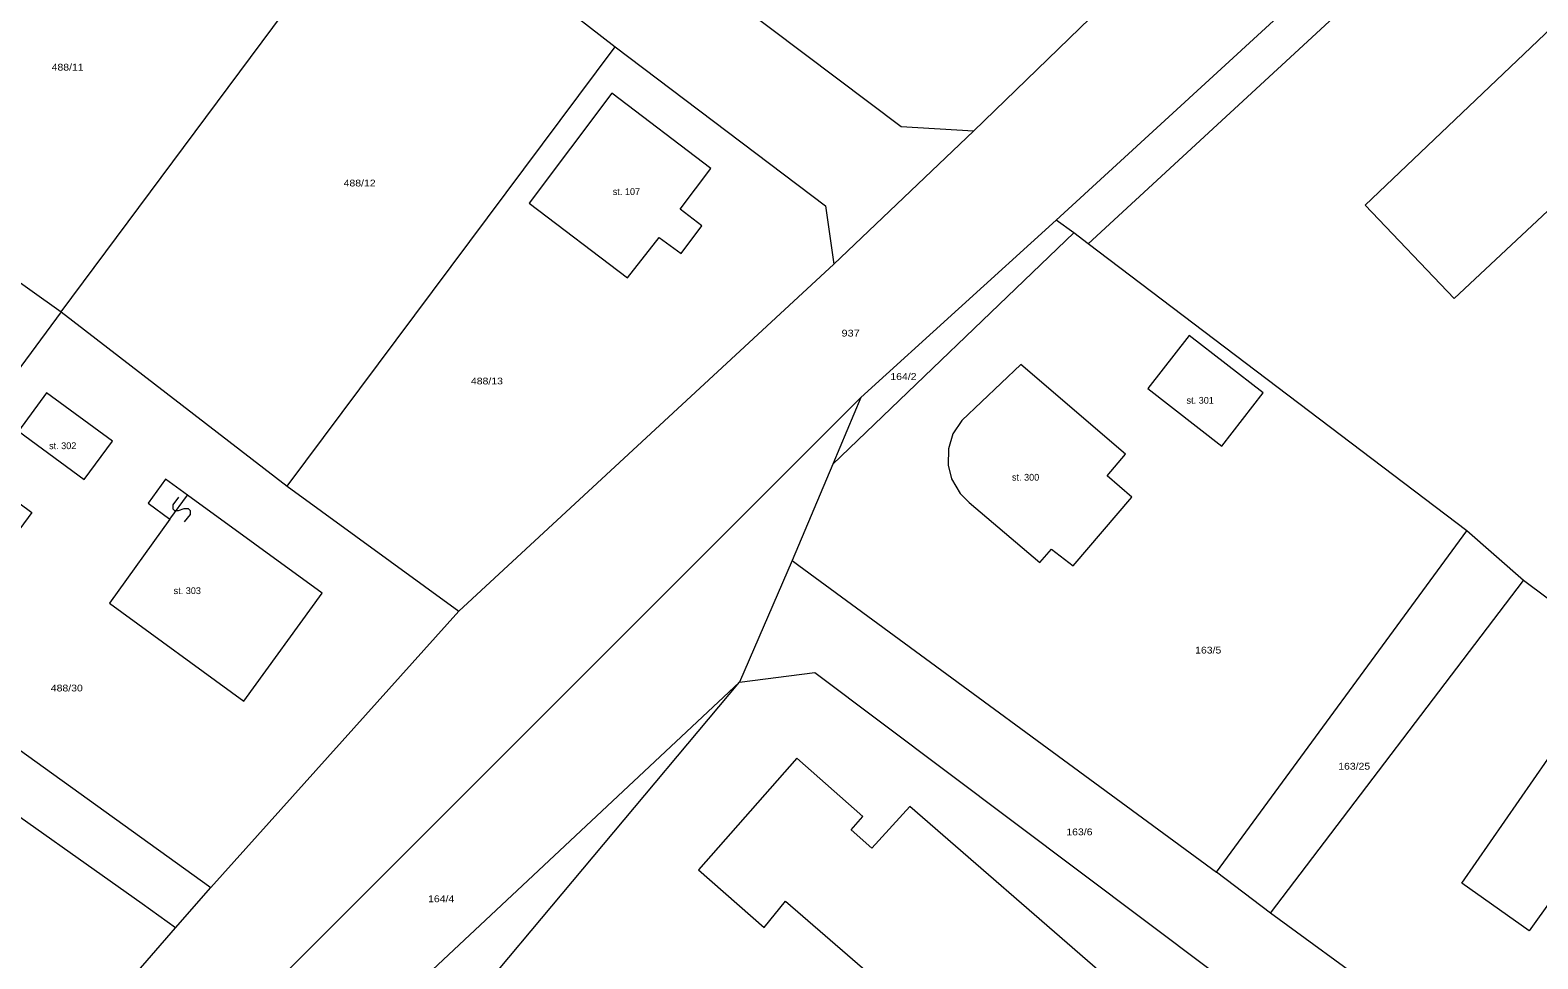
# Model space of a CAD drawing. Extents: x -694702 to -694000, y -1089746 to -1089192.
# Drawn here: x -694548.9 to -694438, y -1089557.5 to -1089489.2 of the extents above; entities that cross this region are included whole.
import ezdxf

# ---------------------------------------------------------------- set-up
doc = ezdxf.new("R2010")
doc.units = 0
doc.header["$LTSCALE"] = 0.2
doc.layers.add('50', color=7, linetype='Continuous', lineweight=13)
doc.layers.add('52', color=7, linetype='Continuous', lineweight=13)

msp = doc.modelspace()

# ---------------------------------------------------------------- linework, layer by layer
at = {"layer": '50'}
for p, q in [((-694479.49, -1089496.59), (-694449.48, -1089467.5)), ((-694546.56, -1089509.88), (-694522.45, -1089477.46)), ((-694522.45, -1089477.46), (-694505.84, -1089490.39)), ((-694529.94, -1089522.69), (-694505.84, -1089490.39)), ((-694489.75, -1089506.36), (-694479.49, -1089496.59)), ((-694473.4, -1089503.12), (-694487.76, -1089516.16)), ((-694472.12, -1089504.07), (-694473.4, -1089503.12)), ((-694472.12, -1089504.07), (-694489.83, -1089521.07)), ((-694471.06, -1089504.87), (-694472.12, -1089504.07)), ((-694443.2, -1089525.98), (-694471.06, -1089504.87)), ((-694517.33, -1089531.88), (-694489.75, -1089506.36)), ((-694546.56, -1089509.88), (-694529.94, -1089522.69)), ((-694487.76, -1089516.16), (-694545.41, -1089573.81)), ((-694487.76, -1089516.16), (-694489.83, -1089521.07)), ((-694489.83, -1089521.07), (-694492.82, -1089528.17)), ((-694529.94, -1089522.69), (-694517.33, -1089531.88)), ((-694538.57, -1089525.13), (-694537.27, -1089523.35)), ((-694461.62, -1089551.07), (-694443.2, -1089525.98)), ((-694439.04, -1089529.64), (-694443.2, -1089525.98)), ((-694492.82, -1089528.17), (-694496.69, -1089537.12)), ((-694457.65, -1089554.09), (-694439.04, -1089529.64)), ((-694435.48, -1089532.3), (-694439.04, -1089529.64)), ((-694535.56, -1089552.2), (-694517.33, -1089531.88)), ((-694457.65, -1089554.09), (-694461.62, -1089551.07)), ((-694538.16, -1089555.18), (-694535.56, -1089552.2)), ((-694430.38, -1089574.01), (-694457.65, -1089554.09))]:
    msp.add_line(p, q, dxfattribs=at)
for points in [[(-694473.4, -1089503.12), (-694446.18, -1089478.12), (-694429.84, -1089464.32)], [(-694471.06, -1089504.87), (-694439.41, -1089475.66), (-694429.16, -1089466.35)], [(-694479.49, -1089496.59), (-694484.8, -1089496.27), (-694499.16, -1089485.42)], [(-694505.84, -1089490.39), (-694490.36, -1089502.08), (-694489.75, -1089506.36)], [(-694558.62, -1089501.3), (-694546.56, -1089509.88), (-694554.38, -1089520.43)], [(-694554.38, -1089520.43), (-694548.72, -1089524.63), (-694557.45, -1089536.48), (-694535.56, -1089552.2)], [(-694492.82, -1089528.17), (-694492.32, -1089528.53), (-694461.62, -1089551.07)], [(-694538.16, -1089555.18), (-694540.61, -1089553.41), (-694565.68, -1089535.66)], [(-694496.69, -1089537.12), (-694521.2, -1089560.09), (-694538.73, -1089578.73)], [(-694450.7, -1089583.15), (-694478.25, -1089618.12), (-694527.15, -1089581.87), (-694528.98, -1089575.65), (-694496.69, -1089537.12)], [(-694496.69, -1089537.12), (-694491.16, -1089536.39), (-694442.58, -1089572.9), (-694443.91, -1089574.53)], [(-694563.76, -1089588.86), (-694559.06, -1089579.24), (-694538.16, -1089555.18)]]:
    msp.add_lwpolyline(points, dxfattribs=at)
for points in [[(-694422.23, -1089474.92), (-694450.69, -1089502.02), (-694444.14, -1089508.9), (-694415.52, -1089482.07), (-694417.72, -1089479.71)], [(-694498.81, -1089499.33), (-694506.09, -1089493.79), (-694512.16, -1089501.89), (-694504.92, -1089507.38), (-694502.59, -1089504.4), (-694500.98, -1089505.59), (-694499.47, -1089503.54), (-694501.06, -1089502.33)], [(-694461.22, -1089519.75), (-694458.18, -1089515.84), (-694463.63, -1089511.61), (-694466.67, -1089515.51)], [(-694474.6, -1089528.31), (-694473.75, -1089527.32), (-694472.16, -1089528.54), (-694467.84, -1089523.51), (-694469.67, -1089521.94), (-694468.3, -1089520.35), (-694476.01, -1089513.74), (-694480.35, -1089517.86), (-694481, -1089518.85), (-694481.33, -1089519.94), (-694481.35, -1089521.16), (-694481.1, -1089522.16), (-694480.47, -1089523.24), (-694479.81, -1089523.89)], [(-694542.8, -1089519.38), (-694547.64, -1089515.83), (-694549.71, -1089518.65), (-694544.87, -1089522.2)], [(-694540.18, -1089523.95), (-694538.57, -1089525.13), (-694543.01, -1089531.31), (-694533.15, -1089538.5), (-694527.37, -1089530.57), (-694537.27, -1089523.35), (-694538.89, -1089522.18)], [(-694435.14, -1089539.74), (-694427.43, -1089545.11), (-694432.76, -1089552.76), (-694435.43, -1089550.92), (-694438.64, -1089555.39), (-694443.59, -1089551.88)], [(-694501.13, -1089577.39), (-694486.01, -1089590.48), (-694480.16, -1089583.83), (-694484.67, -1089579.87), (-694479.32, -1089573.79), (-694483.04, -1089570.52), (-694478.8, -1089565.63), (-694477.44, -1089566.81), (-694470.17, -1089558.42), (-694484.16, -1089546.26), (-694486.96, -1089549.32), (-694488.49, -1089547.96), (-694487.63, -1089546.99), (-694492.48, -1089542.7), (-694499.7, -1089550.91), (-694494.89, -1089555.14), (-694493.3, -1089553.22), (-694480.9, -1089563.95), (-694485.12, -1089568.83), (-694491.17, -1089563.59), (-694498.27, -1089571.8), (-694497.14, -1089572.78)]]:
    msp.add_lwpolyline(points, close=True, dxfattribs=at)
at = {"layer": '52'}
msp.add_lwpolyline([(-694537.95, -1089523.5), (-694538.366, -1089524.063), (-694538.37, -1089524.349), (-694538.228, -1089524.494), (-694537.944, -1089524.484), (-694537.522, -1089524.34), (-694537.243, -1089524.338), (-694537.096, -1089524.475), (-694537.092, -1089524.767), (-694537.515, -1089525.324)], dxfattribs=at)

# ---------------------------------------------------------------- texts
for s, width, p in [('488/11', 1.15, (-694547.27, -1089492.13)), ('488/12', 1.15, (-694525.8, -1089500.65)), ('937', 1.2, (-694489.19, -1089511.69)), ('488/13', 1.15, (-694516.44, -1089515.21)), ('164/2', 1.15, (-694485.6, -1089514.88)), ('163/5', 1.15, (-694463.19, -1089535)), ('488/30', 1.15, (-694547.33, -1089537.79)), ('163/25', 1.15, (-694452.67, -1089543.54)), ('163/6', 1.15, (-694472.66, -1089548.37)), ('164/4', 1.15, (-694519.59, -1089553.29))]:
    msp.add_text(s, height=0.5, dxfattribs=dict(at, width=width)).set_placement(p)
for s, p in [('st. 107', (-694506.01, -1089501.28)), ('st. 301', (-694463.82, -1089516.63)), ('st. 302', (-694547.46, -1089519.97)), ('st. 300', (-694476.66, -1089522.29)), ('st. 303', (-694538.3, -1089530.63))]:
    msp.add_text(s, height=0.5, dxfattribs=at).set_placement(p)

doc.saveas('drawing.dxf')
